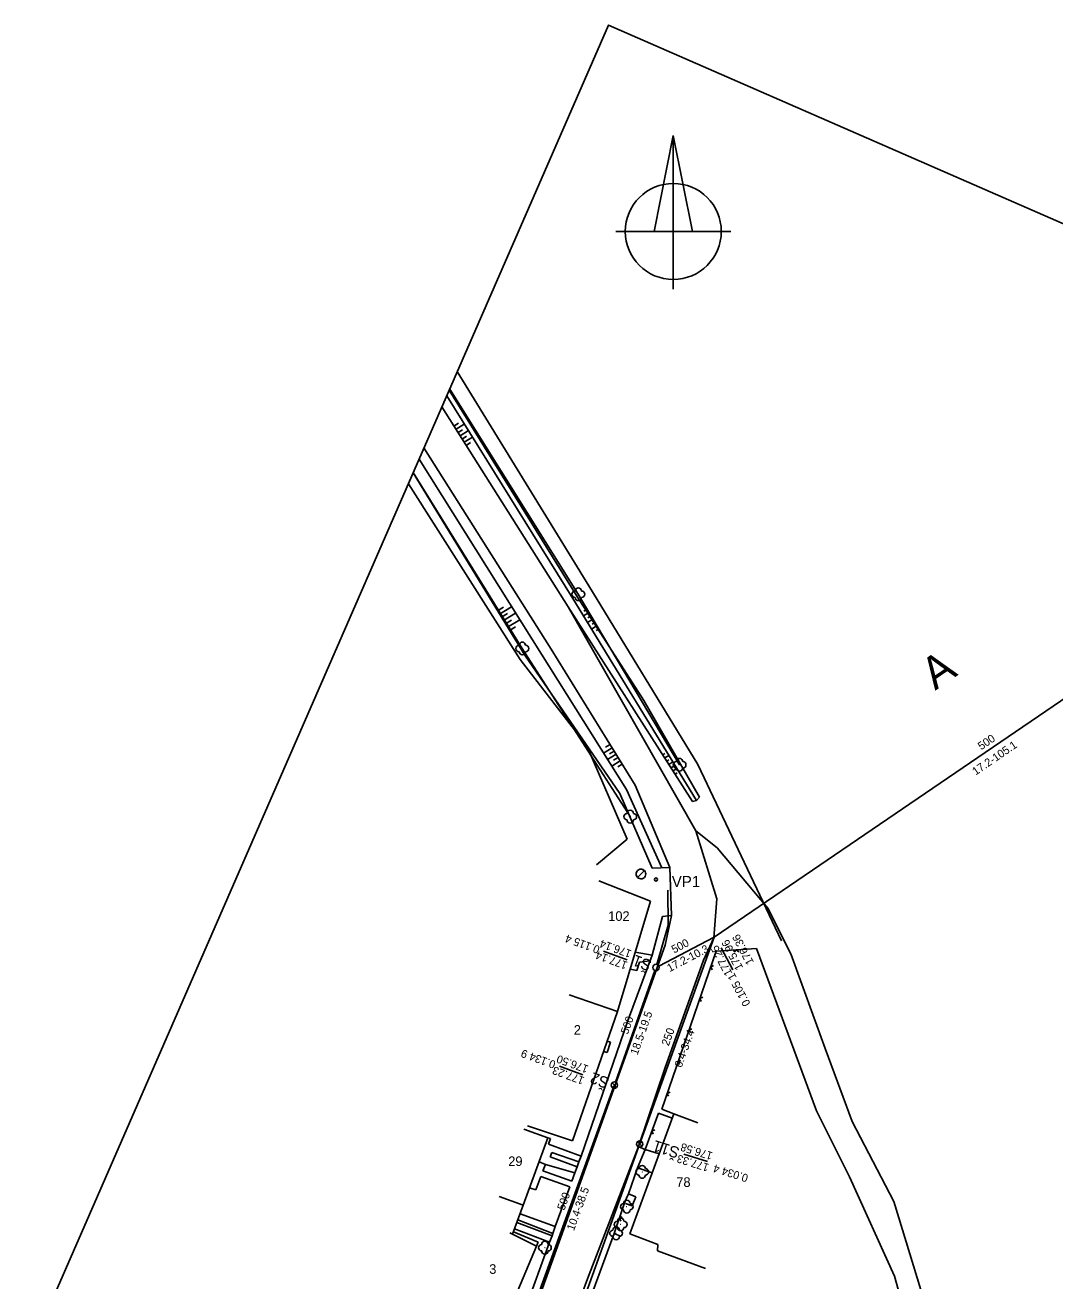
# Model space of a CAD drawing. Extents: x -574526 to -573537, y -1188297 to -1187280.
# Drawn here: x -573900.3 to -573739.4, y -1187476 to -1187279.8 of the extents above; entities that cross this region are included whole.
import ezdxf

# ---------------------------------------------------------------- set-up
doc = ezdxf.new("R2010")
doc.units = 0
for name, color, linetype in [('Vrstva 10', 7, 'Continuous'), ('Vrstva 12', 7, 'Continuous'), ('Vrstva 13', 7, 'Continuous'), ('Vrstva 14', 7, 'Continuous'), ('Vrstva 17', 7, 'Continuous'), ('Vrstva 18', 7, 'Continuous'), ('Vrstva 2', 7, 'Continuous'), ('Vrstva 20', 7, 'Continuous'), ('Vrstva 21', 7, 'Continuous'), ('Vrstva 4', 7, 'Continuous'), ('Vrstva 6', 7, 'Continuous'), ('Vrstva 63', 7, 'Continuous'), ('Vrstva 7', 7, 'Continuous'), ('Vrstva 8', 7, 'Continuous'), ('Vrstva 9', 7, 'Continuous')]:
    doc.layers.add(name, color=color, linetype=linetype)

# ---------------------------------------------------------------- blocks, each defined once
blk = doc.blocks.new('005')
at = {"layer": 'Vrstva 6'}
for p, q in [((0, 30), (-6, 0)), ((0, 30), (0, -18)), ((0, 30), (6, 0)), ((-18, 0), (18, 0))]:
    blk.add_line(p, q, dxfattribs=at)
blk.add_lwpolyline([(0, 30), (6, 0), (0, 0), (0, 30)], close=True, dxfattribs=at)
blk.add_circle((0, 0), 15, dxfattribs=at)
blk = doc.blocks.new('3$130')
at = {"layer": 'Vrstva 8'}
blk.add_circle((0, 0), 0.001, dxfattribs=at)
for centre, start, end in [((-1, 0), 90, 270), ((0, 1), 0, 180), ((1, 0), 270, 90), ((0, -1), 180, 0)]:
    blk.add_arc(centre, 1, start, end, dxfattribs=at)
blk = doc.blocks.new('7$050')
at = {"layer": 'Vrstva 6'}
blk.add_line((1.05, 1.07), (1.05, 1.07), dxfattribs=at)
blk.add_line((1.05, 1.07), (1.05, 1.07), dxfattribs=at)
blk.add_lwpolyline([(-1.07, -1.05), (-1.07, -1.05), (-1, -0.99), (-0.9, -0.89), (-0.76, -0.74), (-0.58, -0.57), (-0.38, -0.36), (-0.17, -0.15), (0.04, 0.06), (0.24, 0.25), (0.43, 0.44), (0.61, 0.63), (0.78, 0.79), (0.92, 0.93), (1.01, 1.03), (0.51, 1.4), (1.05, 1.07), (0.51, 1.4), (0.94, 1.16), (0.84, 1.24), (0.59, 1.38), (1.05, 1.07), (1.05, 1.07), (1.05, 1.07), (1.05, 1.07), (0.3, 1.47), (-0.01, 1.5), (-0.31, 1.47), (-0.6, 1.38), (-0.85, 1.24), (-1.06, 1.06), (-1.24, 0.85), (-1.38, 0.6), (-1.47, 0.31), (-1.5, 0.01), (-1.47, -0.3), (-1.38, -0.59), (-1.24, -0.84), (-1.07, -1.05)], dxfattribs=at)
blk.add_arc((0, 0), 1.5, 224.5943, 45.4084, dxfattribs=at)
blk = doc.blocks.new('6$010')
at = {"layer": 'Vrstva 21'}
blk.add_circle((0, 0), 0.5, dxfattribs=at)
blk = doc.blocks.new('200')
at = {"layer": 'Vrstva 63'}
blk.add_lwpolyline([(0, 0), (210, 0), (210, 297), (0, 297), (0, 0)], close=True, dxfattribs=at)

msp = doc.modelspace()

# ---------------------------------------------------------------- linework, layer by layer
at = {"layer": 'Vrstva 10'}
for p, q in [((-573834.47, -1187337.72), (-573814.77, -1187369.38)), ((-573814.05, -1187369.15), (-573834.07, -1187336.82)), ((-573832.65, -1187342), (-573833.35, -1187342.44)), ((-573831.73, -1187342.13), (-573833.02, -1187342.95)), ((-573832.01, -1187343.02), (-573832.7, -1187343.45)), ((-573831.09, -1187343.14), (-573832.38, -1187343.96)), ((-573831.37, -1187344.03), (-573832.06, -1187344.47)), ((-573830.46, -1187344.16), (-573831.74, -1187344.97)), ((-573830.73, -1187345.04), (-573831.42, -1187345.48)), ((-573821.07, -1187375.85), (-573838.8, -1187347.64)), ((-573822.25, -1187378.26), (-573839.73, -1187349.77)), ((-573803.68, -1187385.34), (-573814.05, -1187369.15)), ((-573825.58, -1187370.72), (-573826.52, -1187371.29)), ((-573824.33, -1187370.66), (-573826.21, -1187371.81)), ((-573796.05, -1187401.08), (-573815.48, -1187370.69)), ((-573814.77, -1187369.38), (-573795.44, -1187400.96)), ((-573813.05, -1187371.37), (-573812.75, -1187371.18)), ((-573824.96, -1187371.74), (-573825.89, -1187372.32)), ((-573823.7, -1187371.67), (-573825.58, -1187372.83)), ((-573824.33, -1187372.76), (-573825.27, -1187373.34)), ((-573823.06, -1187372.69), (-573824.95, -1187373.85)), ((-573813.1, -1187372.11), (-573812.43, -1187371.69)), ((-573812.47, -1187373.14), (-573811.78, -1187372.69)), ((-573812.4, -1187372.38), (-573812.1, -1187372.19)), ((-573823.7, -1187373.79), (-573824.64, -1187374.36)), ((-573811.84, -1187374.16), (-573811.13, -1187373.71)), ((-573811.75, -1187373.39), (-573811.45, -1187373.2)), ((-573811.11, -1187374.4), (-573810.81, -1187374.21)), ((-573806.38, -1187399.22), (-573821.07, -1187375.85)), ((-573807.44, -1187399.83), (-573822.25, -1187378.26)), ((-573794.97, -1187400.39), (-573803.68, -1187385.34)), ((-573809.97, -1187393.52), (-573808.64, -1187392.7)), ((-573809.66, -1187392.62), (-573808.95, -1187392.19)), ((-573809.33, -1187394.53), (-573808.01, -1187393.72)), ((-573809.03, -1187393.64), (-573808.32, -1187393.21)), ((-573808.39, -1187394.66), (-573807.69, -1187394.23)), ((-573800.39, -1187393.58), (-573800.71, -1187393.78)), ((-573799.77, -1187393.89), (-573800.39, -1187394.29)), ((-573799.75, -1187394.59), (-573800.07, -1187394.79)), ((-573808.69, -1187395.55), (-573807.38, -1187394.74)), ((-573807.76, -1187395.68), (-573807.06, -1187395.25)), ((-573799.14, -1187394.91), (-573799.75, -1187395.3)), ((-573799.1, -1187395.6), (-573799.42, -1187395.81)), ((-573798.51, -1187395.94), (-573799.1, -1187396.31)), ((-573798.45, -1187396.61), (-573798.78, -1187396.82)), ((-573807.44, -1187399.83), (-573802.38, -1187411.48)), ((-573800.88, -1187411.43), (-573806.38, -1187399.22)), ((-573795.44, -1187400.96), (-573794.97, -1187400.39)), ((-573796.05, -1187401.08), (-573795.44, -1187400.96)), ((-573802.38, -1187411.48), (-573799.62, -1187411.38))]:
    msp.add_line(p, q, dxfattribs=at)
at = {"layer": 'Vrstva 13'}
for p, q in [((-573789.75, -1187427.4), (-573791.57, -1187423.95)), ((-573806.28, -1187425.81), (-573809.95, -1187424.47)), ((-573813.18, -1187443.76), (-573816.84, -1187442.42)), ((-573793.7, -1187457.34), (-573797.43, -1187456.18))]:
    msp.add_line(p, q, dxfattribs=at)
at = {"layer": 'Vrstva 17'}
for p, q in [((-573808.64, -1187445.74), (-573807.93, -1187445.04)), ((-573808.64, -1187445.04), (-573807.93, -1187445.74)), ((-573804.67, -1187454.94), (-573803.97, -1187454.24)), ((-573804.67, -1187454.24), (-573803.97, -1187454.94))]:
    msp.add_line(p, q, dxfattribs=at)
at = {"layer": 'Vrstva 2'}
for p, q in [((-573705.83, -1187363.12), (-573792.66, -1187422.28)), ((-573804.15, -1187454.12), (-573792.66, -1187422.28)), ((-573801.32, -1187426.79), (-573792.66, -1187422.28)), ((-573808.12, -1187444.92), (-573801.94, -1187427.49)), ((-573821.28, -1187481.09), (-573808.46, -1187445.86)), ((-573824.86, -1187511.59), (-573804.49, -1187455.06))]:
    msp.add_line(p, q, dxfattribs=at)
msp.add_lwpolyline([(-573799.94, -1187414.96), (-573799.85, -1187420.41), (-573801.63, -1187426.54)], dxfattribs=at)
at = {"layer": 'Vrstva 20'}
for points in [[(-573795.53, -1187405.69), (-573792.23, -1187408.34), (-573784.28, -1187417.75), (-573780.7, -1187424.87), (-573775.33, -1187439.65), (-573771.1, -1187451.06), (-573764.6, -1187463.55), (-573752.36, -1187503.61), (-573747.53, -1187527.64), (-573741.93, -1187571.94), (-573742.6, -1187586.18), (-573744.6, -1187605.04), (-573745.68, -1187617.7), (-573745.93, -1187626.03), (-573745.01, -1187633.94), (-573744.51, -1187640.77), (-573743.23, -1187646.67)], [(-573746.49, -1187649.33), (-573747.68, -1187644.77), (-573749.84, -1187629.53), (-573749.84, -1187616.62), (-573746.34, -1187580.64), (-573746.59, -1187572.9), (-573747.09, -1187559.66), (-573752.76, -1187522.68), (-573756.77, -1187503.15), (-573764.52, -1187475.21), (-573771.52, -1187459.72), (-573776.68, -1187449.39), (-573786.08, -1187424.04)]]:
    msp.add_lwpolyline(points, dxfattribs=at)
at = {"layer": 'Vrstva 4'}
for p, q in [((-573812.27, -1187367.43), (-573832.82, -1187333.95)), ((-573813.91, -1187368.72), (-573834.01, -1187336.67)), ((-573840.46, -1187351.45), (-573822.97, -1187378.92)), ((-573839.7, -1187349.71), (-573822.66, -1187377.19)), ((-573798.09, -1187395.36), (-573813.91, -1187368.72)), ((-573795.24, -1187395.3), (-573812.27, -1187367.43)), ((-573822.66, -1187377.19), (-573805.8, -1187403.46)), ((-573782.14, -1187422.87), (-573795.24, -1187395.3)), ((-573806.28, -1187406.98), (-573811.07, -1187410.96))]:
    msp.add_line(p, q, dxfattribs=at)
msp.add_lwpolyline([(-573822.97, -1187378.92), (-573812.57, -1187392.39), (-573806.28, -1187406.98)], dxfattribs=at)
at = {"layer": 'Vrstva 6'}
for p, q in [((-573786.08, -1187424.04), (-573792.36, -1187424.45)), ((-573792.36, -1187424.45), (-573800.87, -1187449.16)), ((-573809.42, -1187440.32), (-573808.88, -1187438.7)), ((-573808.88, -1187438.7), (-573809.4, -1187438.54)), ((-573809.42, -1187440.32), (-573809.95, -1187440.12)), ((-573800.87, -1187449.16), (-573798.99, -1187449.89)), ((-573801.36, -1187449.76), (-573803.48, -1187455.43)), ((-573801.36, -1187449.76), (-573799.25, -1187450.58)), ((-573803.48, -1187455.43), (-573801.29, -1187456.15)), ((-573804.64, -1187458.3), (-573806.08, -1187462.36)), ((-573802.37, -1187459.07), (-573804.64, -1187458.3)), ((-573806.36, -1187463.03), (-573806.68, -1187463.8)), ((-573806.08, -1187462.36), (-573806.36, -1187463.03)), ((-573824.19, -1187468.65), (-573822.51, -1187464.14)), ((-573806.68, -1187463.8), (-573808.32, -1187468.58)), ((-573808.32, -1187468.58), (-573807.31, -1187468.98))]:
    msp.add_line(p, q, dxfattribs=at)
for points in [[(-573788.85, -1187424.57), (-573789.22, -1187424.25), (-573789.55, -1187424.62)], [(-573792.77, -1187426.7), (-573793.21, -1187426.92), (-573792.99, -1187427.37)], [(-573794.47, -1187431.65), (-573794.91, -1187431.86), (-573794.7, -1187432.31)], [(-573796.17, -1187436.59), (-573796.61, -1187436.8), (-573796.4, -1187437.25)], [(-573797.87, -1187441.53), (-573798.32, -1187441.75), (-573798.1, -1187442.19)], [(-573799.57, -1187446.47), (-573800.02, -1187446.69), (-573799.8, -1187447.13)], [(-573801.97, -1187452.39), (-573802.42, -1187452.59), (-573802.21, -1187453.05)], [(-573807.06, -1187465.97), (-573807.5, -1187466.19), (-573807.28, -1187466.63)]]:
    msp.add_lwpolyline(points, dxfattribs=at)
at = {"layer": 'Vrstva 63'}
msp.add_line((-573799.94, -1187414.96), (-573799.94, -1187414.96), dxfattribs=at)
at = {"layer": 'Vrstva 7'}
for p, q in [((-573802.64, -1187416.66), (-573810.71, -1187413.48)), ((-573815.35, -1187431.29), (-573807.79, -1187433.91)), ((-573805.87, -1187468.6), (-573798.99, -1187449.89)), ((-573795.24, -1187451.27), (-573798.99, -1187449.89)), ((-573822.43, -1187452.25), (-573818.67, -1187453.62)), ((-573821.85, -1187451.74), (-573814.81, -1187454.12)), ((-573818.67, -1187453.62), (-573822.51, -1187464.14)), ((-573826.27, -1187462.77), (-573822.51, -1187464.14)), ((-573824.61, -1187468.49), (-573820.44, -1187470.54)), ((-573801.48, -1187470.3), (-573805.87, -1187468.6)), ((-573828.81, -1187490.34), (-573820.44, -1187470.54)), ((-573801.56, -1187471.3), (-573801.48, -1187470.3)), ((-573801.56, -1187471.3), (-573794.05, -1187474.02))]:
    msp.add_line(p, q, dxfattribs=at)
msp.add_lwpolyline([(-573814.81, -1187454.12), (-573807.79, -1187433.91), (-573802.64, -1187416.66)], dxfattribs=at)
at = {"layer": 'Vrstva 8'}
for centre in [(-573801.77, -1187427.02), (-573808.28, -1187445.39), (-573804.32, -1187454.59)]:
    msp.add_circle(centre, 0.5, dxfattribs=at)
at = {"layer": 'Vrstva 9'}
for p, q in [((-573815.48, -1187370.69), (-573835.23, -1187339.46)), ((-573818.17, -1187377.28), (-573838.03, -1187345.87)), ((-573795.53, -1187405.69), (-573815.48, -1187370.69)), ((-573805.03, -1187398.54), (-573818.17, -1187377.28)), ((-573799.62, -1187411.38), (-573805.03, -1187398.54)), ((-573792.27, -1187416.29), (-573795.53, -1187405.69)), ((-573799.62, -1187411.38), (-573799.37, -1187418.88)), ((-573800.75, -1187419.08), (-573802.38, -1187425.09)), ((-573799.37, -1187418.88), (-573800.75, -1187419.08)), ((-573799.37, -1187418.88), (-573800.35, -1187423.54)), ((-573816.88, -1187469.89), (-573800.35, -1187423.54)), ((-573806.23, -1187435.46), (-573802.38, -1187425.09)), ((-573802.38, -1187425.09), (-573805.02, -1187424.64)), ((-573804.35, -1187426.18), (-573802.71, -1187425.97)), ((-573800.37, -1187442.8), (-573794.37, -1187425.87)), ((-573804.79, -1187427.47), (-573805.81, -1187427.29)), ((-573804.79, -1187427.47), (-573804.35, -1187426.18)), ((-573813.48, -1187456.51), (-573806.23, -1187435.46)), ((-573804.5, -1187454.99), (-573800.37, -1187442.8)), ((-573818.24, -1187453.71), (-573818.67, -1187453.62)), ((-573818.57, -1187454.64), (-573818.24, -1187453.71)), ((-573813.48, -1187456.51), (-573818.57, -1187454.64)), ((-573812.5, -1187475.66), (-573804.5, -1187454.99)), ((-573803.48, -1187455.43), (-573804.64, -1187458.3)), ((-573804.5, -1187454.99), (-573803.52, -1187455.45)), ((-573819.05, -1187457.77), (-573820.03, -1187457.35)), ((-573818.32, -1187456.6), (-573818.07, -1187455.93)), ((-573814.09, -1187458.14), (-573818.32, -1187456.6)), ((-573818.07, -1187455.93), (-573813.84, -1187457.38)), ((-573814.09, -1187458.14), (-573813.84, -1187457.38)), ((-573813.84, -1187457.38), (-573813.48, -1187456.51)), ((-573819.43, -1187458.76), (-573819.05, -1187457.77)), ((-573814.91, -1187460.42), (-573819.43, -1187458.76)), ((-573819.05, -1187457.77), (-573814.43, -1187459.11)), ((-573814.43, -1187459.11), (-573814.91, -1187460.42)), ((-573814.43, -1187459.11), (-573814.09, -1187458.14)), ((-573820.54, -1187461.76), (-573819.75, -1187459.65)), ((-573819.75, -1187459.65), (-573815.22, -1187461.27)), ((-573815.22, -1187461.27), (-573817.51, -1187467.47)), ((-573821.52, -1187461.44), (-573820.54, -1187461.76)), ((-573806.08, -1187462.36), (-573804.93, -1187462.82)), ((-573804.93, -1187462.82), (-573805.49, -1187464.27)), ((-573806.53, -1187463.86), (-573805.49, -1187464.27)), ((-573817.98, -1187468.93), (-573823.52, -1187466.87)), ((-573823.37, -1187466.45), (-573817.87, -1187468.55)), ((-573817.51, -1187467.47), (-573823.01, -1187465.5)), ((-573824.05, -1187468.3), (-573820.19, -1187469.93)), ((-573823.88, -1187467.84), (-573818.39, -1187469.91)), ((-573818.39, -1187469.91), (-573817.98, -1187468.93)), ((-573817.87, -1187468.55), (-573817.98, -1187468.93)), ((-573817.87, -1187468.55), (-573817.51, -1187467.47)), ((-573817.09, -1187492.34), (-573808.32, -1187468.58)), ((-573827.08, -1187497.95), (-573816.88, -1187469.89)), ((-573818.39, -1187469.91), (-573822.28, -1187480.62)), ((-573820.44, -1187470.54), (-573820.19, -1187469.93)), ((-573820.96, -1187498.62), (-573812.5, -1187475.66))]:
    msp.add_line(p, q, dxfattribs=at)
msp.add_lwpolyline([(-573794.37, -1187425.87), (-573792.75, -1187422.38), (-573792.27, -1187416.29)], dxfattribs=at)

# ---------------------------------------------------------------- block references
at = {"layer": 'Vrstva 21', "xscale": 0.5, "yscale": 0.5}
msp.add_blockref('6$010', (-573801.78, -1187413.27), dxfattribs=at)
at = {"layer": 'Vrstva 4', "xscale": 0.5, "yscale": 0.5}
for p in [(-573813.91, -1187368.72), (-573822.66, -1187377.19), (-573798.09, -1187395.36), (-573805.8, -1187403.46), (-573803.93, -1187458.94), (-573806.33, -1187464.38), (-573807.29, -1187467.15), (-573808, -1187468.54), (-573819.13, -1187470.79)]:
    msp.add_blockref('3$130', p, dxfattribs=at)
at = {"layer": 'Vrstva 6', "xscale": 0.5, "yscale": 0.5}
msp.add_blockref('7$050', (-573804.12, -1187412.42), dxfattribs=at)
at = {"layer": 'Vrstva 63', "xscale": 3.0000000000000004, "rotation": 66.41577100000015}
msp.add_blockref('200', (-573789.06, -1187976.03), dxfattribs=at)
at = {"layer": 'Vrstva 63', "xscale": 0.5, "yscale": 0.5}
msp.add_blockref('005', (-573799.07, -1187312.05), dxfattribs=at)

# ---------------------------------------------------------------- texts
at = {"layer": 'Vrstva 12'}
for s, p in [('102', (-573809.24, -1187419.74)), ('2', (-573814.62, -1187437.52)), ('29', (-573824.86, -1187458.03)), ('78', (-573798.6, -1187461.29)), ('3', (-573827.83, -1187474.87))]:
    msp.add_text(s, height=1.5, dxfattribs=at).set_placement(p)
at = {"layer": 'Vrstva 13'}
for s, height, rotation, p in [('0.115 4', 1.249, 159.8851, (-573810.44, -1187423.74)), ('176.36', 1.25, 117.8266, (-573786.44, -1187426.2)), ('176.14', 1.249, 159.8851, (-573805.48, -1187424.39)), ('177.25', 1.25, 117.8266, (-573789.8, -1187427.93)), ('175.96', 1.25, 117.8266, (-573788.12, -1187427.04)), ('177.14', 1.249, 159.8851, (-573806.12, -1187426.19)), ('0.105 1', 1.25, 117.8266, (-573786.97, -1187432.68)), ('0.134 9', 1.249, 159.8851, (-573817.34, -1187441.69)), ('176.50', 1.249, 159.8851, (-573812.22, -1187442.4)), ('177.23', 1.249, 159.8851, (-573812.87, -1187444.19)), ('176.58', 1.25, 162.6759, (-573792.81, -1187455.93)), ('177.33', 1.25, 162.6759, (-573793.38, -1187457.75)), ('0.034 4', 1.25, 162.6759, (-573787.26, -1187459.4))]:
    msp.add_text(s, height=height, rotation=rotation, dxfattribs=at).set_placement(p)
at = {"layer": 'Vrstva 14'}
for s, height, rotation, p in [('A', 5, 34.2651, (-573758.15, -1187383.8)), ('500', 1.25, 34.2651, (-573750.95, -1187393.11)), ('17.2-105.1', 1.25, 34.2651, (-573751.83, -1187397.05)), ('17.2-10.3', 1.249, 27.5048, (-573799.65, -1187427.76)), ('500', 1.249, 27.5048, (-573798.95, -1187424.85)), ('18.5-19.5', 1.25, 70.4668, (-573804.66, -1187440.78)), ('500', 1.25, 70.4668, (-573806.16, -1187437.54)), ('250', 1.249, 70.1507, (-573799.79, -1187439.36)), ('6.4-34.4', 1.249, 70.1507, (-573797.78, -1187442.76)), ('10.4-38.5', 1.25, 69.9986, (-573814.6, -1187468.23)), ('500', 1.25, 70.4668, (-573816.09, -1187465.04))]:
    msp.add_text(s, height=height, rotation=rotation, dxfattribs=at).set_placement(p)
at = {"layer": 'Vrstva 18'}
msp.add_text('VP1', height=1.75, dxfattribs=at).set_placement((-573799.3, -1187414.47))
for s, height, rotation, p in [('Š1', 1.749, 159.8851, (-573802.3, -1187425.99)), ('Š2', 1.749, 159.8851, (-573808.94, -1187444.34)), ('Š11', 1.75, 162.6759, (-573797.95, -1187455.21))]:
    msp.add_text(s, height=height, rotation=rotation, dxfattribs=at).set_placement(p)

doc.saveas('drawing.dxf')
